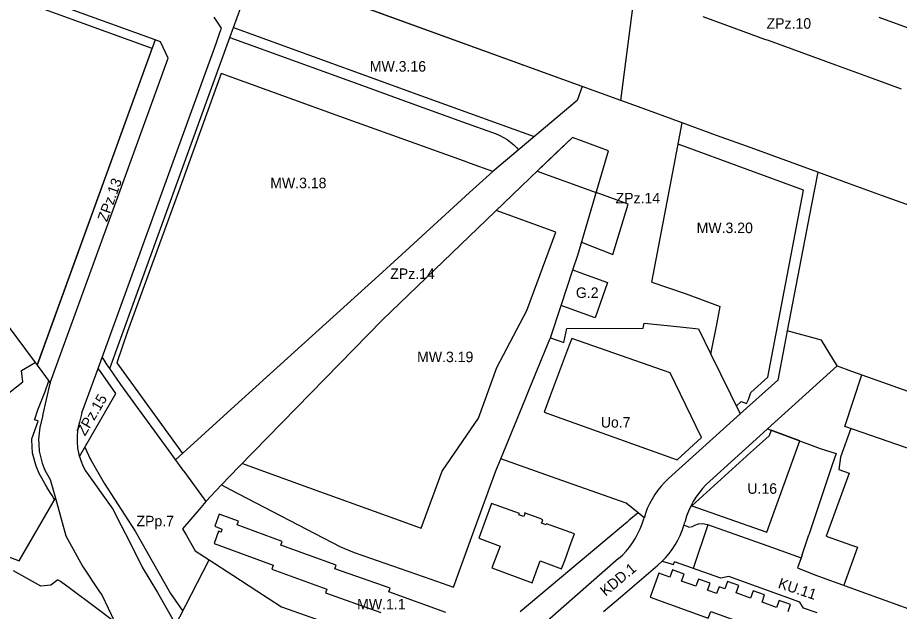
# Model space of a CAD drawing. Extents: x 7428239 to 7429836, y 5549133 to 5550853.
# Drawn here: x 7428593.3 to 7429012.7, y 5549602.4 to 5549884.9 of the extents above; entities that cross this region are included whole.
import ezdxf

# ---------------------------------------------------------------- set-up
doc = ezdxf.new("R2010")
doc.units = 0
for name, color, linetype in [('LIN_linie rozgraniczające', 7, 'Continuous'), ('LIN_nieprzekraczalna linia zabudowy', 7, 'Continuous'), ('LIN_obowiązująca linia zabudowy', 7, 'Continuous'), ('TXT_Oznaczenia Przeznaczenia', 7, 'Continuous')]:
    doc.layers.add(name, color=color, linetype=linetype)

msp = doc.modelspace()

# ---------------------------------------------------------------- linework, layer by layer
at = {"layer": 'LIN_linie rozgraniczające'}
for p, q in [((7428694.29, 5549875.52), (7428706.34, 5549908.74)), ((7428861.9, 5549852.15), (7428716.51, 5549905.02)), ((7428658.74, 5549874.33), (7428602.06, 5549894.89)), ((7428880.21, 5549845.49), (7428886.9, 5549897.16)), ((7428690.31, 5549879.89), (7428686.82, 5549885.14)), ((7428919.18, 5549885.41), (7428930.47, 5549881.33)), ((7429002.91, 5549885.17), (7429018.14, 5549879.67)), ((7428930.47, 5549881.33), (7428935.2, 5549879.6)), ((7428935.2, 5549879.6), (7428948.53, 5549874.76)), ((7428658.74, 5549874.33), (7428602.56, 5549719.6)), ((7428637.14, 5549718.05), (7428694.29, 5549875.52)), ((7428661.35, 5549873.39), (7428658.74, 5549874.33)), ((7428664.94, 5549865.7), (7428661.35, 5549873.39)), ((7428694.29, 5549875.52), (7428757.28, 5549852.67)), ((7428948.53, 5549874.76), (7428950.23, 5549874.14)), ((7428950.23, 5549874.14), (7428982.37, 5549862.43)), ((7428982.37, 5549862.43), (7428997.96, 5549856.76)), ((7428997.96, 5549856.76), (7429013.57, 5549851.08)), ((7428757.28, 5549852.67), (7428780.79, 5549844.15)), ((7428861.9, 5549852.15), (7428859.51, 5549845.56)), ((7428880.21, 5549845.49), (7428861.9, 5549852.15)), ((7428780.79, 5549844.15), (7428804.89, 5549835.39)), ((7428888.67, 5549842.42), (7428880.21, 5549845.49)), ((7428909.34, 5549834.9), (7428888.67, 5549842.42)), ((7428804.89, 5549835.39), (7428820.85, 5549829.61)), ((7428905.53, 5549814.76), (7428909.34, 5549834.9)), ((7428925.79, 5549828.91), (7428909.34, 5549834.9)), ((7428820.85, 5549829.61), (7428822.7, 5549828.85)), ((7428822.7, 5549828.85), (7428824.49, 5549827.95)), ((7428824.49, 5549827.95), (7428826.2, 5549826.91)), ((7428826.2, 5549826.91), (7428827.82, 5549825.74)), ((7428942.23, 5549822.93), (7428925.79, 5549828.91)), ((7428827.82, 5549825.74), (7428829.33, 5549824.43)), ((7428829.33, 5549824.43), (7428830.74, 5549823.01)), ((7428830.74, 5549823.01), (7428831.6, 5549822.06)), ((7428973.94, 5549811.38), (7428942.23, 5549822.93)), ((7428894.97, 5549759.13), (7428905.53, 5549814.76)), ((7428973.94, 5549811.38), (7428970.98, 5549796.03)), ((7428988.92, 5549805.92), (7428973.94, 5549811.38)), ((7429004.61, 5549800.21), (7428988.92, 5549805.92)), ((7429037.75, 5549788.14), (7429004.61, 5549800.21)), ((7428970.98, 5549796.03), (7428959.37, 5549735.85)), ((7428894.97, 5549759.13), (7428911.37, 5549753.49)), ((7428911.37, 5549753.49), (7428927.51, 5549747.56)), ((7428846.71, 5549732.62), (7428851.85, 5549748)), ((7428925.97, 5549739.65), (7428927.51, 5549747.56)), ((7428583.39, 5549745.32), (7428601.61, 5549720.87)), ((7428890.81, 5549737.15), (7428891.27, 5549739.61)), ((7428891.27, 5549739.61), (7428908.37, 5549737.81)), ((7428923.06, 5549724.76), (7428925.97, 5549739.65)), ((7428853.04, 5549730.42), (7428854.5, 5549737.01)), ((7428854.5, 5549737.01), (7428890.81, 5549737.15)), ((7428908.37, 5549737.81), (7428917.12, 5549736.89)), ((7428917.12, 5549736.89), (7428923.06, 5549724.76)), ((7428836.97, 5549708.82), (7428846.46, 5549731.99)), ((7428846.46, 5549731.99), (7428846.71, 5549732.62)), ((7428846.71, 5549732.62), (7428853.04, 5549730.42)), ((7428633.49, 5549723.21), (7428635.17, 5549720.87)), ((7428923.06, 5549724.76), (7428936.97, 5549696.34)), ((7428595.23, 5549717.05), (7428601.61, 5549720.87)), ((7428601.61, 5549720.87), (7428602.56, 5549719.6)), ((7428602.56, 5549719.6), (7428608.87, 5549711.13)), ((7428983.19, 5549719.19), (7428989.92, 5549716.78)), ((7428595.85, 5549711.72), (7428595.23, 5549717.05)), ((7428989.92, 5549716.78), (7428994.89, 5549715)), ((7428538.72, 5549666.5), (7428595.85, 5549711.72)), ((7428605.37, 5549695.57), (7428608.77, 5549710.86)), ((7428608.87, 5549711.13), (7428608.77, 5549710.86)), ((7428608.77, 5549710.86), (7428608.77, 5549710.86)), ((7428650.39, 5549699.51), (7428642.47, 5549710.43)), ((7428834.69, 5549703.26), (7428836.97, 5549708.82)), ((7428823.12, 5549675.01), (7428834.69, 5549703.26)), ((7428658.6, 5549688.17), (7428650.39, 5549699.51)), ((7428605.37, 5549695.57), (7428603.82, 5549690.03)), ((7428603.82, 5549690.03), (7428603.23, 5549684.31)), ((7428666.67, 5549677.04), (7428658.6, 5549688.17)), ((7428603.23, 5549684.31), (7428603.39, 5549682)), ((7428603.39, 5549682), (7428603.62, 5549678.58)), ((7428603.62, 5549678.58), (7428604.97, 5549672.99)), ((7428667.4, 5549676.03), (7428666.67, 5549677.04)), ((7428672.42, 5549669.12), (7428667.4, 5549676.03)), ((7428604.97, 5549672.99), (7428606.28, 5549669.65)), ((7428846.75, 5549666.66), (7428823.12, 5549675.01)), ((7428606.28, 5549669.65), (7428608.8, 5549665.15)), ((7428882.76, 5549653.93), (7428846.75, 5549666.66)), ((7428690.31, 5549662.58), (7428682.87, 5549654.69)), ((7428682.87, 5549654.69), (7428679.69, 5549650.97)), ((7428679.69, 5549650.97), (7428671.75, 5549641.65)), ((7428888.42, 5549649.26), (7428884.25, 5549645.75)), ((7428912.61, 5549642.42), (7428910.22, 5549643.43)), ((7428671.75, 5549641.65), (7428673.56, 5549638.54)), ((7428673.56, 5549638.54), (7428677.76, 5549631.27)), ((7428966.5, 5549629.33), (7428969.68, 5549638.9)), ((7428677.76, 5549631.27), (7428684.4, 5549626.97)), ((7428966.5, 5549629.33), (7428965.96, 5549627.91)), ((7428879.09, 5549627.52), (7428845.3, 5549597.93)), ((7428899.87, 5549626.28), (7428905.2, 5549624.67)), ((7428905.2, 5549624.67), (7428905.77, 5549626.05)), ((7428927.82, 5549618.17), (7428905.77, 5549626.05)), ((7428965.96, 5549627.91), (7428964.18, 5549623.2)), ((7428604.31, 5549614.44), (7428591.41, 5549621.67)), ((7428880.02, 5549609.19), (7428897.89, 5549624.46)), ((7428964.18, 5549623.2), (7428972.53, 5549619.83)), ((7428612.51, 5549617.37), (7428609.16, 5549614.85)), ((7428612.51, 5549617.37), (7428613.69, 5549616.87)), ((7428613.69, 5549616.87), (7428618.42, 5549613.33)), ((7428931.56, 5549619), (7428927.82, 5549618.17)), ((7428965.41, 5549606.73), (7428931.56, 5549619)), ((7428972.53, 5549619.83), (7429033.1, 5549597.79)), ((7428609.16, 5549614.85), (7428604.31, 5549614.44)), ((7428618.42, 5549613.33), (7428630.37, 5549604.36)), ((7428875.05, 5549604.94), (7428880.02, 5549609.19)), ((7428630.37, 5549604.36), (7428639.46, 5549597.54)), ((7428872.04, 5549602.37), (7428875.05, 5549604.94)), ((7428967.1, 5549604.02), (7428965.41, 5549606.73)), ((7428973.59, 5549601.7), (7428967.1, 5549604.02))]:
    msp.add_line(p, q, dxfattribs=at)
for points in [[(7428623.92, 5549696.87), (7428631.58, 5549718.02), (7428633.49, 5549723.21), (7428656.13, 5549785.66), (7428658.86, 5549793.18), (7428687.67, 5549872.61), (7428689.37, 5549877.31), (7428690.31, 5549879.89)], [(7428608.87, 5549711.13), (7428643.37, 5549806.22), (7428664.94, 5549865.7)], [(7428859.51, 5549845.56), (7428819.31, 5549811.71), (7428808.28, 5549801.69), (7428776.03, 5549772.26), (7428765.12, 5549762.29), (7428696.6, 5549700.22), (7428668.44, 5549674.6)], [(7428857.44, 5549764.9), (7428859.77, 5549771.95), (7428874.34, 5549821.62), (7428857.3, 5549827.84), (7428849.38, 5549820.51), (7428766.88, 5549741.19), (7428698.51, 5549671.28), (7428690.31, 5549662.58)], [(7428959.37, 5549735.85), (7428957.87, 5549728.22), (7428954.86, 5549712.48)], [(7428983.19, 5549719.19), (7428975.67, 5549731.48), (7428959.37, 5549735.85)], [(7428639.97, 5549706.1), (7428632.66, 5549716.54), (7428631.58, 5549718.02)], [(7428642.47, 5549710.43), (7428637.14, 5549718.05), (7428635.17, 5549720.87)], [(7428983.19, 5549719.19), (7428950, 5549689.24), (7428946.35, 5549685.95), (7428922.53, 5549664.46)], [(7429019.75, 5549678.94), (7428986.76, 5549690.39), (7428994.89, 5549715), (7429024.38, 5549704.45)], [(7428954.86, 5549712.48), (7428936.97, 5549696.34), (7428902.95, 5549665.65)], [(7428622.72, 5549676.19), (7428639.97, 5549706.1)], [(7428623.92, 5549696.87), (7428622.68, 5549692.43)], [(7428622.68, 5549692.43), (7428622, 5549689.41), (7428621.63, 5549686.34), (7428621.58, 5549683.24), (7428621.86, 5549680.15), (7428622.45, 5549677.11), (7428622.72, 5549676.19), (7428623.35, 5549674.15), (7428624.55, 5549671.3), (7428625.6, 5549669.31)], [(7428950, 5549689.24), (7428975.08, 5549679.97), (7428982.6, 5549677.48), (7428980.7, 5549672.1), (7428969.68, 5549638.9)], [(7428690.31, 5549662.58), (7428694.34, 5549660.48), (7428746.84, 5549633.11), (7428753.4, 5549630.45), (7428789.87, 5549617.8), (7428800.58, 5549613.91), (7428810.5, 5549641.03), (7428820.77, 5549669.27), (7428823.12, 5549675.01)], [(7428625.6, 5549669.31), (7428638.64, 5549650.99), (7428642.6, 5549643.34), (7428646.55, 5549635.7), (7428652.62, 5549623.4), (7428659.85, 5549611.37), (7428677, 5549581.35), (7428685.33, 5549567.22), (7428693.63, 5549552.48), (7428701.86, 5549538.11), (7428711.42, 5549520.42), (7428713.85, 5549514.82), (7428716.28, 5549509.22), (7428717.9, 5549505.9), (7428719.52, 5549502.58), (7428722.28, 5549493.59), (7428725.04, 5549484.59), (7428732.3, 5549464.59), (7428735.09, 5549448.03)], [(7428672.42, 5549669.12), (7428674.45, 5549666.31), (7428682.07, 5549655.79), (7428682.87, 5549654.69)], [(7428538.72, 5549666.5), (7428550.23, 5549654.63), (7428558.81, 5549645.78), (7428567.86, 5549636.45), (7428575.32, 5549633.58), (7428582.79, 5549630.71), (7428594, 5549626.4), (7428611.26, 5549656.29)], [(7428608.8, 5549665.15), (7428611.26, 5549656.29), (7428616.25, 5549638.3), (7428624.11, 5549623.93), (7428632.32, 5549611.66), (7428633.4, 5549610.24), (7428639.46, 5549597.54), (7428640.52, 5549596.75), (7428666.31, 5549550.91), (7428692.12, 5549505.06), (7428695.14, 5549497), (7428701.75, 5549479.01), (7428705.34, 5549469.11), (7428706.25, 5549466.52), (7428708.67, 5549459.09), (7428711.09, 5549451.66), (7428713.12, 5549444.13), (7428728.79, 5549426.29)], [(7428902.95, 5549665.65), (7428901.13, 5549663.9), (7428899.42, 5549662.03), (7428897.83, 5549660.07), (7428896.37, 5549658), (7428895.05, 5549655.85), (7428893.86, 5549653.61), (7428892.81, 5549651.31), (7428891.92, 5549648.94), (7428891.24, 5549646.78)], [(7428922.53, 5549664.46), (7428920.71, 5549662.71), (7428919, 5549660.84), (7428917.41, 5549658.87), (7428915.95, 5549656.81), (7428914.63, 5549654.66), (7428913.44, 5549652.42), (7428912.39, 5549650.12), (7428911.5, 5549647.75), (7428910.75, 5549645.34), (7428910.61, 5549644.81)], [(7428891.28, 5549646.9), (7428888.42, 5549649.26), (7428882.76, 5549653.93)], [(7428879.09, 5549627.52), (7428880.94, 5549629.25), (7428882.68, 5549631.09), (7428884.29, 5549633.03), (7428885.78, 5549635.07), (7428887.14, 5549637.21), (7428888.36, 5549639.42), (7428889.44, 5549641.71), (7428890.37, 5549644.06), (7428891.15, 5549646.47), (7428891.24, 5549646.78)], [(7428884.25, 5549645.75), (7428883.19, 5549644.86), (7428880.57, 5549642.66), (7428832.35, 5549602.13)], [(7428897.89, 5549624.46), (7428899.76, 5549626.16), (7428901.51, 5549627.98), (7428903.15, 5549629.91), (7428904.67, 5549631.93), (7428906.05, 5549634.05), (7428907.3, 5549636.25), (7428908.41, 5549638.53), (7428909.37, 5549640.87), (7428910.18, 5549643.26), (7428910.61, 5549644.81)], [(7428912.61, 5549642.42), (7428914.23, 5549642.74), (7428915.42, 5549643.47), (7428917.09, 5549644.05), (7428919.14, 5549644.22), (7428921.51, 5549643.74), (7428952.4, 5549632.74), (7428965.96, 5549627.91)], [(7428669.26, 5549597.47), (7428670.44, 5549599.77), (7428684.4, 5549626.97)], [(7428684.4, 5549626.97), (7428695.73, 5549619.62), (7428707.06, 5549612.28), (7428718.8, 5549604.66), (7428727.46, 5549601.57), (7428739.98, 5549597.08), (7428750.99, 5549593.15), (7428762.35, 5549589.11), (7428772.73, 5549585.38), (7428783.95, 5549581.36)]]:
    msp.add_lwpolyline(points, dxfattribs=at)
msp.add_lwpolyline([(7428856.55, 5549746.28), (7428851.85, 5549748), (7428857.44, 5549764.9), (7428860.79, 5549763.67), (7428873.9, 5549758.84), (7428868.09, 5549742.07)], close=True, dxfattribs=at)
at = {"layer": 'LIN_nieprzekraczalna linia zabudowy'}
for p, q in [((7428950.15, 5549713.8), (7428967.09, 5549802.9)), ((7428921.6, 5549643.59), (7428914.6, 5549622.89))]:
    msp.add_line(p, q, dxfattribs=at)
for points in [[(7428602.56, 5549719.6), (7428657.24, 5549870.2), (7428600.92, 5549890.64), (7428567.79, 5549902.64), (7428511.65, 5549922.99), (7428459.3, 5549941.54), (7428453.98, 5549937.74)], [(7428861.9, 5549852.15), (7428716.51, 5549905.02), (7428706.34, 5549908.74)], [(7428695.99, 5549880.21), (7428711.16, 5549874.7), (7428787.1, 5549847.15), (7428839.01, 5549828.3)], [(7428819.33, 5549811.72), (7428808.66, 5549815.58), (7428805.37, 5549816.76), (7428746.57, 5549837.94), (7428690.17, 5549858.41), (7428669.77, 5549802.04), (7428645.54, 5549735.6), (7428640.45, 5549720.76), (7428671.74, 5549677.61)], [(7428857.3, 5549827.84), (7428840.45, 5549811.92), (7428868.5, 5549801.72)], [(7428967.09, 5549802.9), (7428940.24, 5549812.71), (7428907.41, 5549824.69)], [(7428861.57, 5549778.07), (7428876.46, 5549772.23), (7428883.66, 5549796.21), (7428868.5, 5549801.72)], [(7428700.28, 5549672.82), (7428727.75, 5549662.87), (7428772.54, 5549646.61), (7428785.31, 5549641.98), (7428795.19, 5549669.12), (7428812.47, 5549694.43), (7428821.28, 5549718.5), (7428835.57, 5549745.63), (7428849.3, 5549782.88), (7428820.95, 5549793.17)], [(7428903.7, 5549715.92), (7428856.89, 5549732.34), (7428855.64, 5549729.03), (7428846.6, 5549705.02), (7428843.75, 5549697.19), (7428907.04, 5549674.52), (7428918.65, 5549685.12), (7428903.7, 5549715.92)], [(7428937.53, 5549702.35), (7428940.06, 5549701.29), (7428940.87, 5549703.23), (7428942.08, 5549706.49), (7428950.15, 5549713.8)], [(7428607.33, 5549661.3), (7428606.82, 5549662.16), (7428603.49, 5549668.01), (7428602.06, 5549671.54), (7428600.37, 5549677.71), (7428600.04, 5549684), (7428600.05, 5549684.6), (7428603.07, 5549692.89), (7428602.92, 5549693.03), (7428601.36, 5549693.6), (7428601.45, 5549693.87), (7428602.99, 5549698.26), (7428605.2, 5549703.84), (7428606.36, 5549707.01), (7428608.15, 5549712.1)], [(7428935.11, 5549700.14), (7428937.53, 5549702.35)], [(7428965.38, 5549683.56), (7428951.7, 5549688.61), (7428950.73, 5549685.97), (7428947.81, 5549683.3), (7428944.68, 5549680.56), (7428941.95, 5549678.08), (7428914.03, 5549652.68), (7428949.67, 5549640.09), (7428952.54, 5549648.04), (7428965.38, 5549683.56)], [(7428989.65, 5549689.39), (7428984.66, 5549675.79), (7428983.83, 5549669.94), (7428988.79, 5549668.17), (7428977.92, 5549638.28), (7428989.98, 5549633.95), (7428992.82, 5549632.93), (7428986.24, 5549614.84)], [(7428625.22, 5549680.53), (7428627.89, 5549675), (7428628.35, 5549674.17), (7428634.44, 5549663.4), (7428649.22, 5549640.52), (7428666.06, 5549610.9), (7428671.83, 5549602.49)], [(7428610.83, 5549655.56), (7428609.71, 5549657.52), (7428607.38, 5549661.2), (7428606.84, 5549662.14)]]:
    msp.add_lwpolyline(points, dxfattribs=at)
at = {"layer": 'LIN_obowiązująca linia zabudowy'}
msp.add_lwpolyline([(7428822.81, 5549633.47), (7428818.94, 5549623.07), (7428838.05, 5549616.02), (7428841.87, 5549626.41), (7428852.06, 5549622.62), (7428853.54, 5549626.66), (7428856.66, 5549635.14), (7428858.19, 5549639.25), (7428844.94, 5549644.1), (7428844.74, 5549643.56), (7428842.48, 5549644.4), (7428842.89, 5549645.55), (7428843.01, 5549645.55), (7428843.19, 5549646.03), (7428841.8, 5549646.54), (7428835.93, 5549648.71), (7428834.49, 5549649.24), (7428834.35, 5549648.81), (7428834.5, 5549648.76), (7428834.03, 5549647.49), (7428831.77, 5549648.33), (7428832, 5549648.92), (7428818.75, 5549653.81), (7428812.62, 5549637.29)], close=True, dxfattribs=at)
for points in [[(7428796.91, 5549601.89), (7428769.94, 5549611.65), (7428770.51, 5549613.44), (7428744.25, 5549622.63), (7428744.81, 5549624.42), (7428718.56, 5549633.97), (7428719.13, 5549635.65), (7428697.76, 5549643.61), (7428698.39, 5549645.4), (7428689.19, 5549648.72), (7428687.04, 5549642.92), (7428690.47, 5549641.58), (7428690.05, 5549640.17), (7428688.82, 5549640.57), (7428686.74, 5549634.73), (7428714.88, 5549624.44), (7428714.29, 5549622.49), (7428740.37, 5549612.93), (7428739.82, 5549611.23), (7428766.02, 5549601.84)], [(7428959.79, 5549602.37), (7428960.99, 5549605.7), (7428955.54, 5549607.66), (7428954.33, 5549604.3), (7428947.38, 5549606.8), (7428948.62, 5549610.26), (7428943.17, 5549612.22), (7428941.91, 5549608.74), (7428935.01, 5549611.22), (7428936.29, 5549614.79), (7428930.95, 5549616.71), (7428929.67, 5549613.14), (7428927.04, 5549614.09), (7428925.77, 5549610.88), (7428921.43, 5549612.44), (7428922.63, 5549615.78), (7428917.11, 5549617.76), (7428915.91, 5549614.42), (7428909.12, 5549616.86), (7428910.32, 5549620.2), (7428904.72, 5549622.21), (7428903.47, 5549618.72), (7428898.33, 5549620.56), (7428894.23, 5549609.12), (7428921.79, 5549599.21), (7428923, 5549602.44), (7428960.41, 5549588.86)]]:
    msp.add_lwpolyline(points, dxfattribs=at)

# ---------------------------------------------------------------- texts
at = {"layer": 'TXT_Oznaczenia Przeznaczenia'}
for s, p in [('ZPz.10', (7428949.54, 5549879.66)), ('MW.3.16', (7428760.82, 5549859.25)), ('MW.3.18', (7428713.46, 5549803.77)), ('ZPz.14', (7428877.72, 5549796.56)), ('MW.3.20', (7428916.27, 5549782.41)), ('ZPz.14', (7428770.54, 5549760.59)), ('G.2', (7428858.85, 5549751.56)), ('MW.3.19', (7428783.32, 5549721.01)), ('Uo.7', (7428870.69, 5549689.88)), ('U.16', (7428940.41, 5549658.37)), ('ZPp.7', (7428649.83, 5549642.92)), ('MW.1.1', (7428754.81, 5549603.37))]:
    msp.add_text(s, height=5, dxfattribs=at).set_placement(p)
for s, rotation, p in [('ZPz.13', 70.1273, (7428635.83, 5549787.48)), ('ZPz.15', 59.5458, (7428625.37, 5549685.57)), ('KDD.1', 39.9338, (7428872.95, 5549609.39)), ('KU.11', 341.6825, (7428954.65, 5549613.7))]:
    msp.add_text(s, height=5, rotation=rotation, dxfattribs=at).set_placement(p)

doc.saveas('drawing.dxf')
